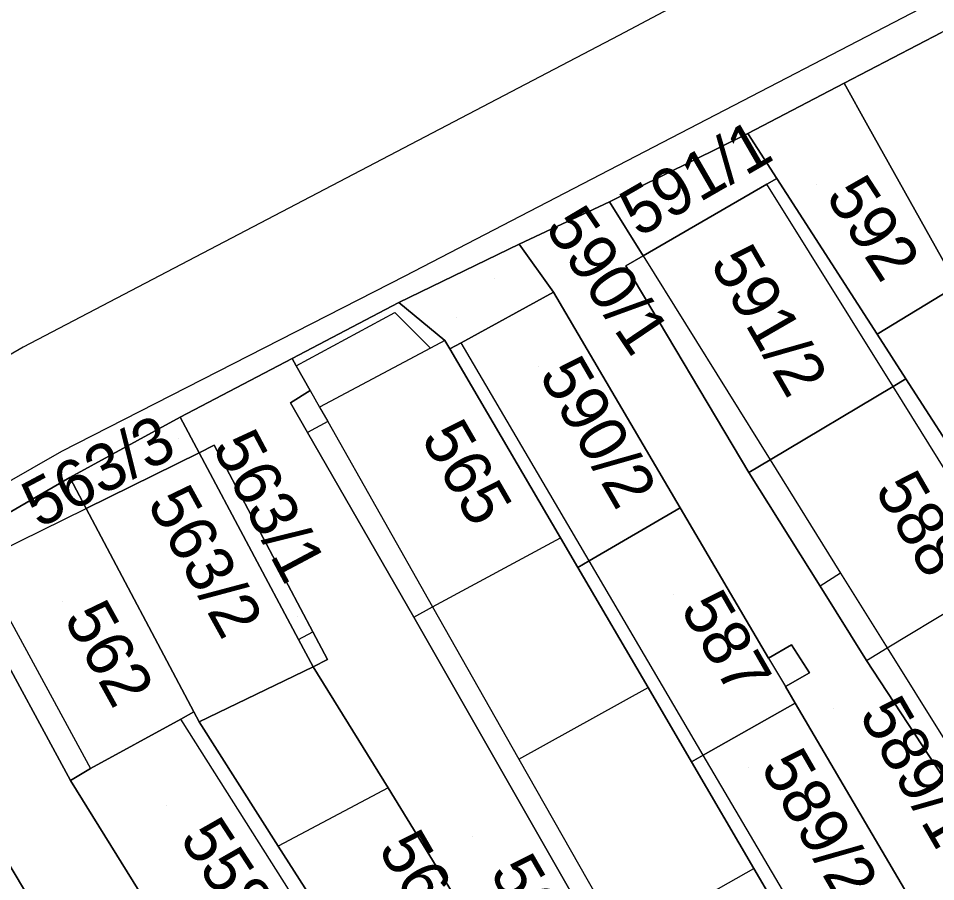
# Model space of a CAD drawing. Extents: x -263943 to -261149, y -1236934 to -1230686.
# Drawn here: x -262686.94 to -262648.22, y -1235426.02 to -1235389.57 of the extents above; entities that cross this region are included whole.
import ezdxf

# ---------------------------------------------------------------- set-up
doc = ezdxf.new("R2010")
doc.units = 0
for name, color, linetype in [('body_kn', 7, 'Continuous'), ('kladpar_druhypozemkov', 7, 'Continuous'), ('kladpar_hranice', 7, 'Continuous'), ('kladpar_parcelnecisla', 7, 'Continuous'), ('kladpar_plochy', 7, 'Continuous'), ('kladpar_sipky', 7, 'Continuous'), ('zappar_hrandruhpozemk', 7, 'Continuous')]:
    doc.layers.add(name, color=color, linetype=linetype)

msp = doc.modelspace()

# ---------------------------------------------------------------- linework, layer by layer
at = {"layer": 'body_kn'}
for p, q in [((-262661.59, -1235390.29), (-262661.59, -1235390.29)), ((-262652.08, -1235392.3), (-262652.08, -1235392.3)), ((-262651.08, -1235394.1), (-262651.08, -1235394.1)), ((-262656.15, -1235394.43), (-262656.15, -1235394.43)), ((-262656.15, -1235394.43), (-262656.15, -1235394.43)), ((-262654.93, -1235396.33), (-262654.93, -1235396.33)), ((-262655.34, -1235396.57), (-262655.34, -1235396.57)), ((-262661.99, -1235397.32), (-262661.99, -1235397.32)), ((-262665.8, -1235399.1), (-262665.8, -1235399.1)), ((-262660.57, -1235399.6), (-262660.57, -1235399.6)), ((-262660.57, -1235399.6), (-262660.57, -1235399.6)), ((-262661.3, -1235400.02), (-262661.3, -1235400.02)), ((-262670.63, -1235400.46), (-262670.63, -1235400.46)), ((-262664.35, -1235401.13), (-262664.35, -1235401.13)), ((-262670.88, -1235401.57), (-262670.88, -1235401.57)), ((-262671.05, -1235401.99), (-262671.05, -1235401.99)), ((-262650.69, -1235402.91), (-262650.69, -1235402.91)), ((-262650.69, -1235402.91), (-262650.69, -1235402.91)), ((-262668.93, -1235403.17), (-262668.93, -1235403.17)), ((-262668.93, -1235403.17), (-262668.93, -1235403.17)), ((-262668.25, -1235403.27), (-262668.25, -1235403.27)), ((-262686.74, -1235403.46), (-262686.74, -1235403.46)), ((-262669.54, -1235403.49), (-262669.54, -1235403.49)), ((-262669.54, -1235403.49), (-262669.54, -1235403.49)), ((-262668.72, -1235403.52), (-262668.72, -1235403.52)), ((-262668.72, -1235403.52), (-262668.72, -1235403.52)), ((-262675.38, -1235403.93), (-262675.38, -1235403.93)), ((-262675.21, -1235404.24), (-262675.21, -1235404.24)), ((-262675.21, -1235404.24), (-262675.21, -1235404.24)), ((-262649.48, -1235404.79), (-262649.48, -1235404.79)), ((-262649.48, -1235404.79), (-262649.48, -1235404.79)), ((-262674.62, -1235405.28), (-262674.62, -1235405.28)), ((-262674.62, -1235405.28), (-262674.62, -1235405.28)), ((-262650.02, -1235405.12), (-262650.02, -1235405.12)), ((-262650.02, -1235405.12), (-262650.02, -1235405.12)), ((-262675.45, -1235405.81), (-262675.45, -1235405.81)), ((-262674.22, -1235405.99), (-262674.22, -1235405.99)), ((-262680.11, -1235406.41), (-262680.11, -1235406.41)), ((-262673.88, -1235406.59), (-262673.88, -1235406.59)), ((-262674.73, -1235407.06), (-262674.73, -1235407.06)), ((-262678.67, -1235407.59), (-262678.67, -1235407.59)), ((-262685.11, -1235407.86), (-262685.11, -1235407.86)), ((-262679.31, -1235407.91), (-262679.31, -1235407.91)), ((-262679.31, -1235407.91), (-262679.31, -1235407.91)), ((-262655.21, -1235408.21), (-262655.21, -1235408.21)), ((-262655.21, -1235408.21), (-262655.21, -1235408.21)), ((-262656.11, -1235408.74), (-262656.11, -1235408.74)), ((-262684.77, -1235408.96), (-262684.77, -1235408.96)), ((-262684.77, -1235408.96), (-262684.77, -1235408.96)), ((-262684.08, -1235410.26), (-262684.08, -1235410.26)), ((-262659, -1235410.24), (-262659, -1235410.24)), ((-262664.06, -1235411.5), (-262664.06, -1235411.5)), ((-262664.06, -1235411.5), (-262664.06, -1235411.5)), ((-262662.84, -1235412.48), (-262662.84, -1235412.48)), ((-262662.84, -1235412.48), (-262662.84, -1235412.48)), ((-262663.32, -1235412.76), (-262663.32, -1235412.76)), ((-262663.32, -1235412.76), (-262663.32, -1235412.76)), ((-262652.23, -1235413), (-262652.23, -1235413)), ((-262652.23, -1235413), (-262652.23, -1235413)), ((-262653.1, -1235413.55), (-262653.1, -1235413.55)), ((-262669.45, -1235414.42), (-262669.45, -1235414.42)), ((-262669.45, -1235414.42), (-262669.45, -1235414.42)), ((-262670.25, -1235414.86), (-262670.25, -1235414.86)), ((-262670.25, -1235414.86), (-262670.25, -1235414.86)), ((-262675.11, -1235415.8), (-262675.11, -1235415.8)), ((-262675.11, -1235415.8), (-262675.11, -1235415.8)), ((-262674.51, -1235415.48), (-262674.51, -1235415.48)), ((-262654.31, -1235416.02), (-262654.31, -1235416.02)), ((-262650.27, -1235416.15), (-262650.27, -1235416.15)), ((-262650.27, -1235416.15), (-262650.27, -1235416.15)), ((-262674.5, -1235416.95), (-262674.5, -1235416.95)), ((-262674.5, -1235416.95), (-262674.5, -1235416.95)), ((-262673.89, -1235416.65), (-262673.89, -1235416.65)), ((-262655.27, -1235416.58), (-262655.27, -1235416.58)), ((-262655.27, -1235416.58), (-262655.27, -1235416.58)), ((-262651.14, -1235416.69), (-262651.14, -1235416.69)), ((-262651.14, -1235416.69), (-262651.14, -1235416.69)), ((-262653.54, -1235417.2), (-262653.54, -1235417.2)), ((-262653.54, -1235417.2), (-262653.54, -1235417.2)), ((-262660.36, -1235417.83), (-262660.36, -1235417.83)), ((-262654.56, -1235417.79), (-262654.56, -1235417.79)), ((-262654.15, -1235418.49), (-262654.15, -1235418.49)), ((-262679.53, -1235418.86), (-262679.53, -1235418.86)), ((-262680.08, -1235419.16), (-262680.08, -1235419.16)), ((-262679.31, -1235419.28), (-262679.31, -1235419.28)), ((-262658.03, -1235420.68), (-262658.03, -1235420.68)), ((-262658.03, -1235420.68), (-262658.03, -1235420.68)), ((-262665.81, -1235420.85), (-262665.81, -1235420.85)), ((-262658.53, -1235420.96), (-262658.53, -1235420.96)), ((-262683.89, -1235421.24), (-262683.89, -1235421.24)), ((-262683.89, -1235421.24), (-262683.89, -1235421.24)), ((-262684.73, -1235421.75), (-262684.73, -1235421.75)), ((-262671.33, -1235422.06), (-262671.33, -1235422.06)), ((-262671.33, -1235422.06), (-262671.33, -1235422.06)), ((-262675.97, -1235424.52), (-262675.97, -1235424.52)), ((-262655.89, -1235425.47), (-262655.89, -1235425.47))]:
    msp.add_line(p, q, dxfattribs=at)
at = {"layer": 'kladpar_druhypozemkov'}
for p, q in [((-262659.09, -1235396.61), (-262659.09, -1235396.61)), ((-262653.23, -1235396.58), (-262653.23, -1235396.58)), ((-262668.43, -1235402.21), (-262668.43, -1235402.21)), ((-262654.55, -1235402.07), (-262654.55, -1235402.07)), ((-262664.98, -1235404.28), (-262664.98, -1235404.28)), ((-262680.18, -1235407.3), (-262680.18, -1235407.3)), ((-262667.37, -1235408.25), (-262667.37, -1235408.25)), ((-262678.18, -1235412.4), (-262678.18, -1235412.4)), ((-262685.09, -1235414.21), (-262685.09, -1235414.21)), ((-262659.28, -1235413.88), (-262659.28, -1235413.88)), ((-262675.15, -1235414.83), (-262675.15, -1235414.83)), ((-262652.53, -1235418.73), (-262652.53, -1235418.73)), ((-262656.11, -1235421.21), (-262656.11, -1235421.21)), ((-262680.69, -1235422.81), (-262680.69, -1235422.81)), ((-262667.77, -1235424.11), (-262667.77, -1235424.11))]:
    msp.add_line(p, q, dxfattribs=at)
at = {"layer": 'kladpar_hranice'}
for points in [[(-262609.74, -1235370.97), (-262625.92, -1235379.04), (-262632.53, -1235382.25), (-262636.42, -1235384.14), (-262642.9, -1235387.52), (-262643.49, -1235387.83), (-262647.97, -1235390.16), (-262652.08, -1235392.3), (-262656.15, -1235394.43), (-262661.99, -1235397.32), (-262665.8, -1235399.1), (-262670.88, -1235401.57), (-262675.38, -1235403.93), (-262680.11, -1235406.41), (-262684.77, -1235408.96), (-262689.17, -1235411.51), (-262693.37, -1235413.97), (-262697.3, -1235416.27), (-262702.63, -1235419.24), (-262706.44, -1235421.37), (-262709.75, -1235423.15), (-262714.15, -1235426.04)], [(-262647.31, -1235400.85), (-262651.08, -1235394.1), (-262652.08, -1235392.3), (-262647.97, -1235390.16)], [(-262656.15, -1235394.43), (-262652.08, -1235392.3), (-262651.08, -1235394.1), (-262647.31, -1235400.85), (-262650.69, -1235402.91), (-262654.93, -1235396.33), (-262656.15, -1235394.43)], [(-262660.57, -1235399.6), (-262661.99, -1235397.32), (-262656.15, -1235394.43), (-262654.93, -1235396.33), (-262655.34, -1235396.57), (-262660.57, -1235399.6)], [(-262649.48, -1235404.79), (-262650.02, -1235405.12), (-262655.21, -1235408.21), (-262656.11, -1235408.74), (-262661.3, -1235400.02), (-262660.57, -1235399.6), (-262655.34, -1235396.57), (-262654.93, -1235396.33), (-262650.69, -1235402.91), (-262649.48, -1235404.79)], [(-262649.53, -1235426.34), (-262654.15, -1235418.49), (-262654.56, -1235417.79), (-262653.54, -1235417.2), (-262654.31, -1235416.02), (-262655.27, -1235416.58), (-262659, -1235410.24), (-262664.35, -1235401.13), (-262665.8, -1235399.1), (-262661.99, -1235397.32), (-262660.57, -1235399.6), (-262661.3, -1235400.02), (-262656.11, -1235408.74), (-262653.1, -1235413.55), (-262651.14, -1235416.69), (-262646.14, -1235424.3), (-262640.83, -1235432.46)], [(-262668.72, -1235403.52), (-262668.93, -1235403.17), (-262670.88, -1235401.57), (-262665.8, -1235399.1), (-262664.35, -1235401.13), (-262668.25, -1235403.27), (-262668.72, -1235403.52)], [(-262650.69, -1235402.91), (-262647.31, -1235400.85), (-262643.49, -1235406.96), (-262646.79, -1235408.96), (-262649.48, -1235404.79), (-262650.69, -1235402.91)], [(-262664.06, -1235411.5), (-262668.72, -1235403.52), (-262668.25, -1235403.27), (-262664.35, -1235401.13), (-262659, -1235410.24), (-262662.84, -1235412.48), (-262663.32, -1235412.76), (-262664.06, -1235411.5)], [(-262663.32, -1235412.76), (-262660.36, -1235417.83), (-262658.53, -1235420.96), (-262655.89, -1235425.47), (-262653.84, -1235428.97), (-262653.36, -1235429.71), (-262659, -1235432.88), (-262659.72, -1235433.28), (-262670.25, -1235414.86), (-262674.73, -1235407.06), (-262675.45, -1235405.81), (-262674.62, -1235405.28), (-262675.21, -1235404.24), (-262675.38, -1235403.93), (-262670.88, -1235401.57), (-262668.93, -1235403.17), (-262668.72, -1235403.52), (-262664.06, -1235411.5), (-262663.32, -1235412.76)], [(-262665.79, -1235431.11), (-262671.33, -1235422.06), (-262674.5, -1235416.95), (-262673.89, -1235416.65), (-262674.51, -1235415.48), (-262678.67, -1235407.59), (-262679.31, -1235407.91), (-262680.11, -1235406.41), (-262675.38, -1235403.93), (-262675.21, -1235404.24), (-262674.62, -1235405.28), (-262675.45, -1235405.81), (-262674.73, -1235407.06), (-262670.25, -1235414.86), (-262659.72, -1235433.28)], [(-262639.54, -1235420.22), (-262640.3, -1235420.73), (-262645.46, -1235423.87), (-262646.14, -1235424.3), (-262651.14, -1235416.69), (-262653.1, -1235413.55), (-262656.11, -1235408.74), (-262655.21, -1235408.21), (-262650.02, -1235405.12), (-262649.48, -1235404.79), (-262646.79, -1235408.96), (-262644.15, -1235413.06), (-262643.49, -1235414.08), (-262639.54, -1235420.22)], [(-262684.77, -1235408.96), (-262680.11, -1235406.41), (-262679.31, -1235407.91), (-262684.08, -1235410.26), (-262684.77, -1235408.96)], [(-262679.31, -1235407.91), (-262678.67, -1235407.59), (-262674.51, -1235415.48), (-262673.89, -1235416.65), (-262674.5, -1235416.95), (-262675.11, -1235415.8), (-262679.31, -1235407.91)], [(-262674.5, -1235416.95), (-262679.31, -1235419.28), (-262679.53, -1235418.86), (-262684.08, -1235410.26), (-262679.31, -1235407.91), (-262675.11, -1235415.8), (-262674.5, -1235416.95)], [(-262683.89, -1235421.24), (-262684.73, -1235421.75), (-262688.28, -1235415.22), (-262689.51, -1235412.95), (-262688.63, -1235412.51), (-262689.17, -1235411.51), (-262684.77, -1235408.96), (-262684.08, -1235410.26), (-262679.53, -1235418.86), (-262680.08, -1235419.16), (-262683.89, -1235421.24)], [(-262653.54, -1235417.2), (-262654.56, -1235417.79), (-262654.15, -1235418.49), (-262658.03, -1235420.68), (-262658.53, -1235420.96), (-262660.36, -1235417.83), (-262663.32, -1235412.76), (-262662.84, -1235412.48), (-262659, -1235410.24), (-262655.27, -1235416.58), (-262654.31, -1235416.02), (-262653.54, -1235417.2)], [(-262684.79, -1235429.54), (-262688.2, -1235423.87), (-262689.35, -1235421.67), (-262693.37, -1235413.97), (-262689.17, -1235411.51), (-262688.63, -1235412.51), (-262689.51, -1235412.95), (-262688.28, -1235415.22), (-262684.73, -1235421.75), (-262680.64, -1235428.35)], [(-262668.43, -1235436.33), (-262670.13, -1235433.66), (-262671.47, -1235431.56), (-262675.97, -1235424.52), (-262679.31, -1235419.28), (-262674.5, -1235416.95), (-262671.33, -1235422.06), (-262665.79, -1235431.11), (-262664.14, -1235433.63), (-262663.9, -1235433.99), (-262664.3, -1235434.24), (-262668.21, -1235436.67), (-262668.43, -1235436.33)], [(-262653.34, -1235428.66), (-262653.84, -1235428.97), (-262655.89, -1235425.47), (-262658.53, -1235420.96), (-262658.03, -1235420.68), (-262654.15, -1235418.49), (-262649.53, -1235426.34), (-262650.19, -1235426.74), (-262653.34, -1235428.66)], [(-262677.32, -1235434.96), (-262681.4, -1235428.77), (-262680.64, -1235428.35), (-262684.73, -1235421.75), (-262683.89, -1235421.24), (-262680.08, -1235419.16), (-262679.53, -1235418.86), (-262679.31, -1235419.28), (-262675.97, -1235424.52), (-262671.47, -1235431.56), (-262672.02, -1235431.88), (-262676.6, -1235434.54), (-262677.32, -1235434.96)], [(-262672.61, -1235447.81), (-262675.7, -1235449.74), (-262676.59, -1235448.24), (-262677.69, -1235446.62), (-262680.6, -1235442.32), (-262682.68, -1235439.11), (-262683.94, -1235437.16), (-262687.47, -1235431.69), (-262687.69, -1235431.35), (-262691.25, -1235425.83), (-262688.2, -1235423.87), (-262684.79, -1235429.54), (-262679.77, -1235437.24), (-262674.91, -1235444.93), (-262673.75, -1235446.39), (-262672.61, -1235447.81)]]:
    msp.add_lwpolyline(points, dxfattribs=at)
at = {"layer": 'kladpar_plochy'}
for p, q in [((-262647.97, -1235390.16), (-262652.08, -1235392.3)), ((-262652.08, -1235392.3), (-262656.15, -1235394.43)), ((-262656.15, -1235394.43), (-262661.99, -1235397.32)), ((-262661.99, -1235397.32), (-262665.8, -1235399.1)), ((-262665.8, -1235399.1), (-262670.88, -1235401.57)), ((-262670.88, -1235401.57), (-262675.38, -1235403.93)), ((-262675.38, -1235403.93), (-262680.11, -1235406.41)), ((-262680.11, -1235406.41), (-262684.77, -1235408.96)), ((-262684.77, -1235408.96), (-262689.17, -1235411.51))]:
    msp.add_line(p, q, dxfattribs=at)
for points in [[(-262647.31, -1235400.85), (-262651.08, -1235394.1), (-262652.08, -1235392.3), (-262647.97, -1235390.16)], [(-262649.53, -1235426.34), (-262654.15, -1235418.49), (-262654.56, -1235417.79), (-262653.54, -1235417.2), (-262654.31, -1235416.02), (-262655.27, -1235416.58), (-262659, -1235410.24), (-262664.35, -1235401.13), (-262665.8, -1235399.1), (-262661.99, -1235397.32), (-262660.57, -1235399.6), (-262661.3, -1235400.02), (-262656.11, -1235408.74), (-262653.1, -1235413.55), (-262651.14, -1235416.69), (-262646.14, -1235424.3), (-262640.83, -1235432.46)], [(-262665.79, -1235431.11), (-262671.33, -1235422.06), (-262674.5, -1235416.95), (-262673.89, -1235416.65), (-262674.51, -1235415.48), (-262678.67, -1235407.59), (-262679.31, -1235407.91), (-262680.11, -1235406.41), (-262675.38, -1235403.93), (-262675.21, -1235404.24), (-262674.62, -1235405.28), (-262675.45, -1235405.81), (-262674.73, -1235407.06), (-262670.25, -1235414.86), (-262659.72, -1235433.28)], [(-262684.79, -1235429.54), (-262688.2, -1235423.87), (-262689.35, -1235421.67), (-262693.37, -1235413.97), (-262689.17, -1235411.51), (-262688.63, -1235412.51), (-262689.51, -1235412.95), (-262688.28, -1235415.22), (-262684.73, -1235421.75), (-262680.64, -1235428.35)]]:
    msp.add_lwpolyline(points, dxfattribs=at)
for points in [[(-262656.15, -1235394.43), (-262652.08, -1235392.3), (-262651.08, -1235394.1), (-262647.31, -1235400.85), (-262650.69, -1235402.91), (-262654.93, -1235396.33)], [(-262660.57, -1235399.6), (-262661.99, -1235397.32), (-262656.15, -1235394.43), (-262654.93, -1235396.33), (-262655.34, -1235396.57)], [(-262649.48, -1235404.79), (-262650.02, -1235405.12), (-262655.21, -1235408.21), (-262656.11, -1235408.74), (-262661.3, -1235400.02), (-262660.57, -1235399.6), (-262655.34, -1235396.57), (-262654.93, -1235396.33), (-262650.69, -1235402.91)], [(-262668.72, -1235403.52), (-262668.93, -1235403.17), (-262670.88, -1235401.57), (-262665.8, -1235399.1), (-262664.35, -1235401.13), (-262668.25, -1235403.27)], [(-262650.69, -1235402.91), (-262647.31, -1235400.85), (-262643.49, -1235406.96), (-262646.79, -1235408.96), (-262649.48, -1235404.79)], [(-262664.06, -1235411.5), (-262668.72, -1235403.52), (-262668.25, -1235403.27), (-262664.35, -1235401.13), (-262659, -1235410.24), (-262662.84, -1235412.48), (-262663.32, -1235412.76)], [(-262663.32, -1235412.76), (-262660.36, -1235417.83), (-262658.53, -1235420.96), (-262655.89, -1235425.47), (-262653.84, -1235428.97), (-262653.36, -1235429.71), (-262659, -1235432.88), (-262659.72, -1235433.28), (-262670.25, -1235414.86), (-262674.73, -1235407.06), (-262675.45, -1235405.81), (-262674.62, -1235405.28), (-262675.21, -1235404.24), (-262675.38, -1235403.93), (-262670.88, -1235401.57), (-262668.93, -1235403.17), (-262668.72, -1235403.52), (-262664.06, -1235411.5)], [(-262639.54, -1235420.22), (-262640.3, -1235420.73), (-262645.46, -1235423.87), (-262646.14, -1235424.3), (-262651.14, -1235416.69), (-262653.1, -1235413.55), (-262656.11, -1235408.74), (-262655.21, -1235408.21), (-262650.02, -1235405.12), (-262649.48, -1235404.79), (-262646.79, -1235408.96), (-262644.15, -1235413.06), (-262643.49, -1235414.08)], [(-262684.77, -1235408.96), (-262680.11, -1235406.41), (-262679.31, -1235407.91), (-262684.08, -1235410.26)], [(-262679.31, -1235407.91), (-262678.67, -1235407.59), (-262674.51, -1235415.48), (-262673.89, -1235416.65), (-262674.5, -1235416.95), (-262675.11, -1235415.8)], [(-262674.5, -1235416.95), (-262679.31, -1235419.28), (-262679.53, -1235418.86), (-262684.08, -1235410.26), (-262679.31, -1235407.91), (-262675.11, -1235415.8)], [(-262683.89, -1235421.24), (-262684.73, -1235421.75), (-262688.28, -1235415.22), (-262689.51, -1235412.95), (-262688.63, -1235412.51), (-262689.17, -1235411.51), (-262684.77, -1235408.96), (-262684.08, -1235410.26), (-262679.53, -1235418.86), (-262680.08, -1235419.16)], [(-262653.54, -1235417.2), (-262654.56, -1235417.79), (-262654.15, -1235418.49), (-262658.03, -1235420.68), (-262658.53, -1235420.96), (-262660.36, -1235417.83), (-262663.32, -1235412.76), (-262662.84, -1235412.48), (-262659, -1235410.24), (-262655.27, -1235416.58), (-262654.31, -1235416.02)], [(-262668.43, -1235436.33), (-262670.13, -1235433.66), (-262671.47, -1235431.56), (-262675.97, -1235424.52), (-262679.31, -1235419.28), (-262674.5, -1235416.95), (-262671.33, -1235422.06), (-262665.79, -1235431.11), (-262664.14, -1235433.63), (-262663.9, -1235433.99), (-262664.3, -1235434.24), (-262668.21, -1235436.67)], [(-262653.34, -1235428.66), (-262653.84, -1235428.97), (-262655.89, -1235425.47), (-262658.53, -1235420.96), (-262658.03, -1235420.68), (-262654.15, -1235418.49), (-262649.53, -1235426.34), (-262650.19, -1235426.74)], [(-262677.32, -1235434.96), (-262681.4, -1235428.77), (-262680.64, -1235428.35), (-262684.73, -1235421.75), (-262683.89, -1235421.24), (-262680.08, -1235419.16), (-262679.53, -1235418.86), (-262679.31, -1235419.28), (-262675.97, -1235424.52), (-262671.47, -1235431.56), (-262672.02, -1235431.88), (-262676.6, -1235434.54)], [(-262672.61, -1235447.81), (-262675.7, -1235449.74), (-262676.59, -1235448.24), (-262677.69, -1235446.62), (-262680.6, -1235442.32), (-262682.68, -1235439.11), (-262683.94, -1235437.16), (-262687.47, -1235431.69), (-262687.69, -1235431.35), (-262691.25, -1235425.83), (-262688.2, -1235423.87), (-262684.79, -1235429.54), (-262679.77, -1235437.24), (-262674.91, -1235444.93), (-262673.75, -1235446.39)]]:
    msp.add_lwpolyline(points, close=True, dxfattribs=at)
at = {"layer": 'kladpar_sipky'}
msp.add_line((-262666.85, -1235400.56), (-262666.85, -1235400.56), dxfattribs=at)
at = {"layer": 'zappar_hrandruhpozemk'}
for p, q in [((-262661.59, -1235390.29), (-262686.74, -1235403.46)), ((-262650.02, -1235405.12), (-262655.34, -1235396.57)), ((-262660.57, -1235399.6), (-262655.21, -1235408.21)), ((-262670.63, -1235400.46), (-262685.11, -1235407.86)), ((-262675.21, -1235404.24), (-262671.05, -1235401.99)), ((-262671.05, -1235401.99), (-262669.54, -1235403.49)), ((-262668.93, -1235403.17), (-262669.54, -1235403.49)), ((-262662.84, -1235412.48), (-262668.25, -1235403.27)), ((-262669.54, -1235403.49), (-262674.22, -1235405.99)), ((-262645.1, -1235413.03), (-262650.02, -1235405.12)), ((-262673.88, -1235406.59), (-262674.73, -1235407.06)), ((-262688.63, -1235412.51), (-262684.08, -1235410.26)), ((-262669.45, -1235414.42), (-262664.06, -1235411.5)), ((-262658.03, -1235420.68), (-262662.84, -1235412.48)), ((-262652.23, -1235413), (-262653.1, -1235413.55)), ((-262650.27, -1235416.15), (-262645.1, -1235413.03)), ((-262670.25, -1235414.86), (-262669.45, -1235414.42)), ((-262675.11, -1235415.8), (-262674.51, -1235415.48)), ((-262651.14, -1235416.69), (-262650.27, -1235416.15)), ((-262655.27, -1235416.58), (-262654.56, -1235417.79)), ((-262665.81, -1235420.85), (-262660.36, -1235417.83)), ((-262672.02, -1235431.88), (-262680.08, -1235419.16)), ((-262653.34, -1235428.66), (-262658.03, -1235420.68)), ((-262671.33, -1235422.06), (-262675.97, -1235424.52)), ((-262661.43, -1235428.58), (-262655.89, -1235425.47))]:
    msp.add_line(p, q, dxfattribs=at)
for points in [[(-262588.16, -1235355.95), (-262598.75, -1235358.84), (-262613.91, -1235366.32), (-262626.61, -1235372.53), (-262642.53, -1235380.17), (-262661.59, -1235390.29)], [(-262588.06, -1235360.35), (-262596.11, -1235362.9), (-262626.26, -1235377.86), (-262637.27, -1235383.13), (-262670.63, -1235400.46)], [(-262686.74, -1235403.46), (-262715.86, -1235420.37), (-262741.68, -1235435.75), (-262772.15, -1235455.63), (-262791.2, -1235467.95), (-262809.56, -1235480.1)], [(-262674.62, -1235405.28), (-262674.22, -1235405.99), (-262673.88, -1235406.59)], [(-262673.88, -1235406.59), (-262669.45, -1235414.42), (-262665.81, -1235420.85)], [(-262685.11, -1235407.86), (-262717.88, -1235426.64), (-262739.97, -1235440.83), (-262767.48, -1235458.75), (-262796.08, -1235477.45), (-262799.98, -1235480), (-262806.92, -1235484.25), (-262811.15, -1235486.8)], [(-262655.21, -1235408.21), (-262652.23, -1235413), (-262650.27, -1235416.15), (-262645.46, -1235423.87)], [(-262688.63, -1235412.51), (-262687.4, -1235414.78), (-262683.89, -1235421.24)], [(-262665.81, -1235420.85), (-262661.43, -1235428.58), (-262659, -1235432.88)]]:
    msp.add_lwpolyline(points, dxfattribs=at)

# ---------------------------------------------------------------- texts
at = {"layer": 'kladpar_parcelnecisla'}
for s, rotation, p in [('591/1', 30, (-262660.766, -1235398.844)), ('592', 303, (-262652.898, -1235397.078)), ('590/1', 304, (-262664.747, -1235398.388)), ('591/2', 300, (-262657.772, -1235399.904)), ('590/2', 300, (-262664.992, -1235404.622)), ('563/3', 28, (-262686.066, -1235411.131)), ('565', 300, (-262669.971, -1235407.293)), ('563/1', 298, (-262678.781, -1235407.656)), ('588', 300, (-262650.821, -1235409.463)), ('563/2', 299, (-262681.531, -1235410.039)), ('587', 300, (-262659.025, -1235414.495)), ('562', 299, (-262685.048, -1235414.9)), ('589/1', 300, (-262651.484, -1235418.972)), ('589/2', 300, (-262655.642, -1235421.182)), ('558/2', 303, (-262680.163, -1235424.196)), ('566/1', 300, (-262671.778, -1235424.629)), ('564', 300, (-262667.063, -1235425.631))]:
    msp.add_text(s, height=2, rotation=rotation, dxfattribs=at).set_placement(p)

doc.saveas('drawing.dxf')
